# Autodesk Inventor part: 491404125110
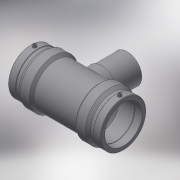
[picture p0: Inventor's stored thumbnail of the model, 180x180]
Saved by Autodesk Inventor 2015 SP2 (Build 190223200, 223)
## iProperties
Created: 2017-06
Part Number: 491404125110
Material: Generic
Description: PLASSON REDUCING TEE 125x110x125
Document SubType Name: Modeling
Designer: KIM
Mass: 3175.88 g
Surface Area: 4079.53 cm^2
Volume: 3175.88 cm^3
Density: 1 g/cm^3
Appearance: Default
Author: KIM
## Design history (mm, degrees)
derived "491404.ipt"
feature "Solid1::491404.ipt"
tag "TaggingFeature1"
body "Solid1"
other parameters: "d0" = 382, "d1" = 125, "d2" = 165, "d3" = 86, "d4" = 76.4, "d5" = 148.5, "d6" = 118.75, "d7" = 125, "d8" = 168 deg, "d10" = 34.4, "d11" = 11.46667, "d13" = 382, "d14" = 17.6296, "d17" = 112.5, "d18" = 125, "d19" = 3.52592, "d20" = 168 deg, "d22" = 153.45, "d23" = 165, "d25" = 135 deg, "d26" = 267.4, "d29" = 88, "d30" = 15, "d31" = 152.8, "d34" = 5 deg, "d35" = 15, "d39" = 5 deg, "d41" = 4, "d42" = 14, "d43" = 0, "d45" = 4, "d46" = 6, "d47" = 0, "d48" = -173, "d51" = 0, "d52" = 88, "d54" = 0, "d55" = 148.5, "d56" = 165, "d57" = 133.7, "d58" = 135 deg, "d59" = 86, "d60" = 86, "d61" = 135 deg, "d62" = 173, "d72" = 173.81, "d73" = 86.905, "d74" = -173, "d75" = 115.5, "d77" = 0, "d78" = 88, "d80" = 0, "d82" = 90.5, "d83" = 0, "d84" = 3, "d85" = 0, "d86" = 28.66667, "d87" = 150.381, "d88" = 11.46667, "d89" = 3, "d90" = 0, "d_" = 125, "L_" = 382, "L_1" = 86, "D_" = 165, "A_" = 88, "d_2" = 12, "H_" = 173
